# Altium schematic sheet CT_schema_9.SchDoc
size 274 x 160 mm
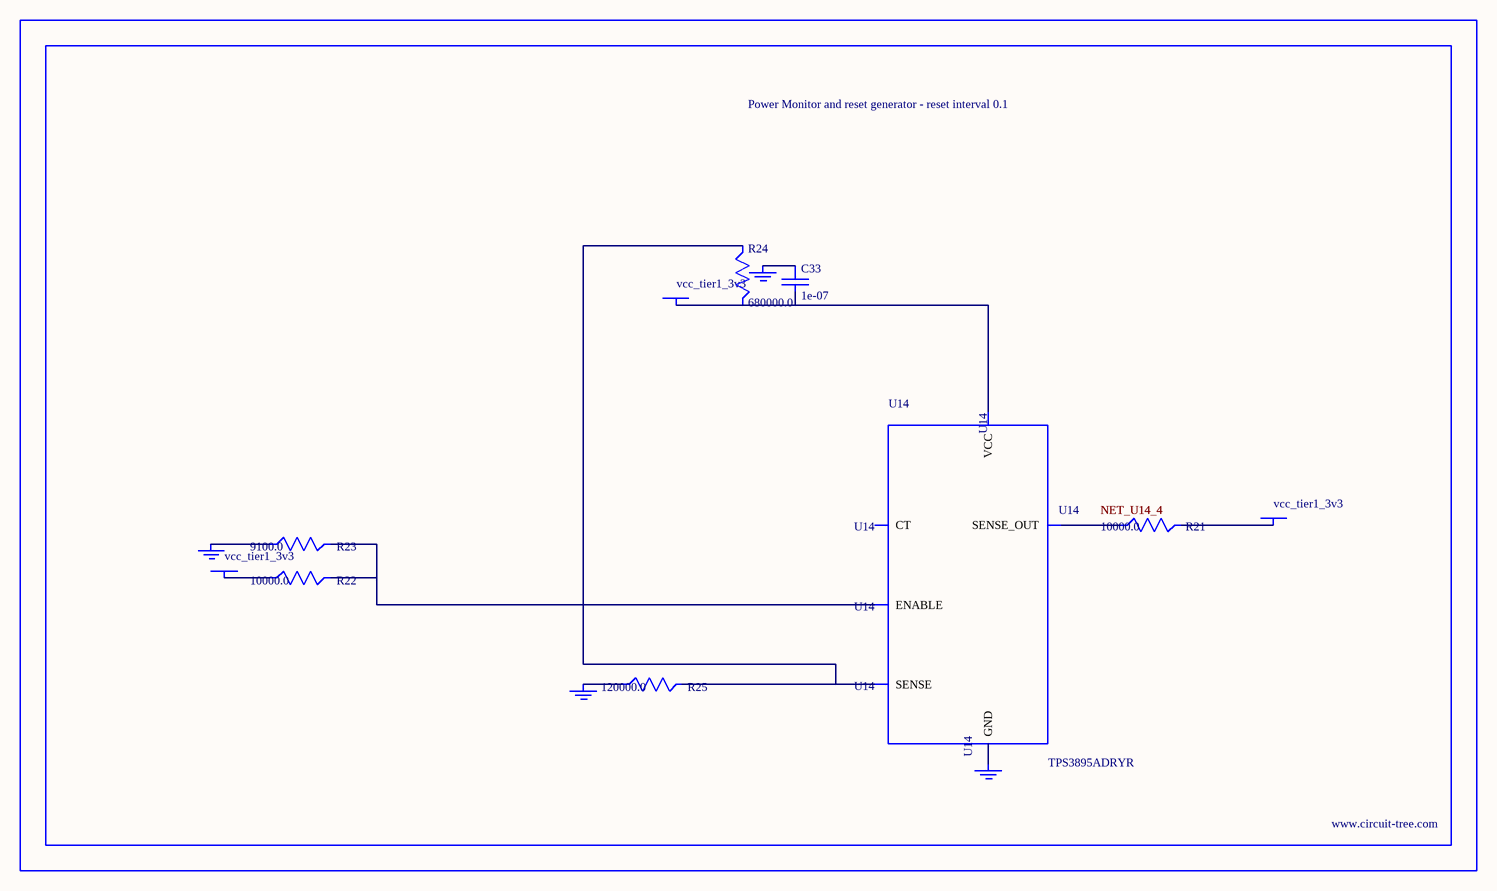
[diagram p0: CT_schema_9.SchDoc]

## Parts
BORDER8  (no value)
C33  1e-07  [C0402]
GND_INSTANCE_8_0  (no value)
GND_INSTANCE_8_1  (no value)
GND_INSTANCE_8_2  (no value)
GND_INSTANCE_8_3  (no value)
POWER_INSTANCE_8_0  vcc_tier1_3v3
POWER_INSTANCE_8_1  vcc_tier1_3v3
POWER_INSTANCE_8_2  vcc_tier1_3v3
R21  10000.0  [R0603]
R22  10000.0  [R0603]
R23  9100.0  [R0603]
R24  680000.0  [R0603]
R25  120000.0  [R0603]
U14  TPS3895ADRYR  [SON-6]

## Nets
NetC33_1: C33.1 GND_INSTANCE_8_2.0(GND)
NetC33_2: C33.2 POWER_INSTANCE_8_2.0(PWR) R24.2 U14.6(VCC)
NetGND_INSTANCE_8_0_0: GND_INSTANCE_8_0.0(GND) R23.1
NetGND_INSTANCE_8_1_0: GND_INSTANCE_8_1.0(GND) R25.1
NetGND_INSTANCE_8_3_0: GND_INSTANCE_8_3.0(GND) U14.2(GND)
NetPOWER_INSTANCE_8_0_0: POWER_INSTANCE_8_0.0(PWR) R22.1
NetPOWER_INSTANCE_8_1_0: POWER_INSTANCE_8_1.0(PWR) R21.2
NetR21_1: R21.1 U14.4(SENSE_OUT)
NetR22_2: R22.2 R23.2 U14.1(ENABLE)
NetR24_1: R24.1 R25.2 U14.3(SENSE)

Not connected (* = marked no-connect by the designer): U14 5(CT)

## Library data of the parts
BORDER8 = BORDER_PAGE8
C33 = C0402C104K3RACTU
GND_INSTANCE_8_0-GND_INSTANCE_8_3 = GND
POWER_INSTANCE_8_0-POWER_INSTANCE_8_2 = PWR
R21 R22 = RC0603JR-0710KL
R23 = RC0603JR-079K1L
R24 = RC0603JR-07680KL
R25 = RC0603JR-07120KL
